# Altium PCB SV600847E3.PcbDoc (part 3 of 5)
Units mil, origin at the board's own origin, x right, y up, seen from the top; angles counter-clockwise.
Board outline 5404 x 2680 mil, 10 copper layers (Top Layer L1, Gnd-Plane - L2, Signals - L3, Gnd-Plane - L4, Pwr Plane - L5, Signals - L6, Gnd-Plane - L7, Signals - L8, Gnd-Plane - L9, Bottom Layer - L10), stack 57.8 mil thick; 517 components, 320 nets, 1784 pads, 1289 vias.
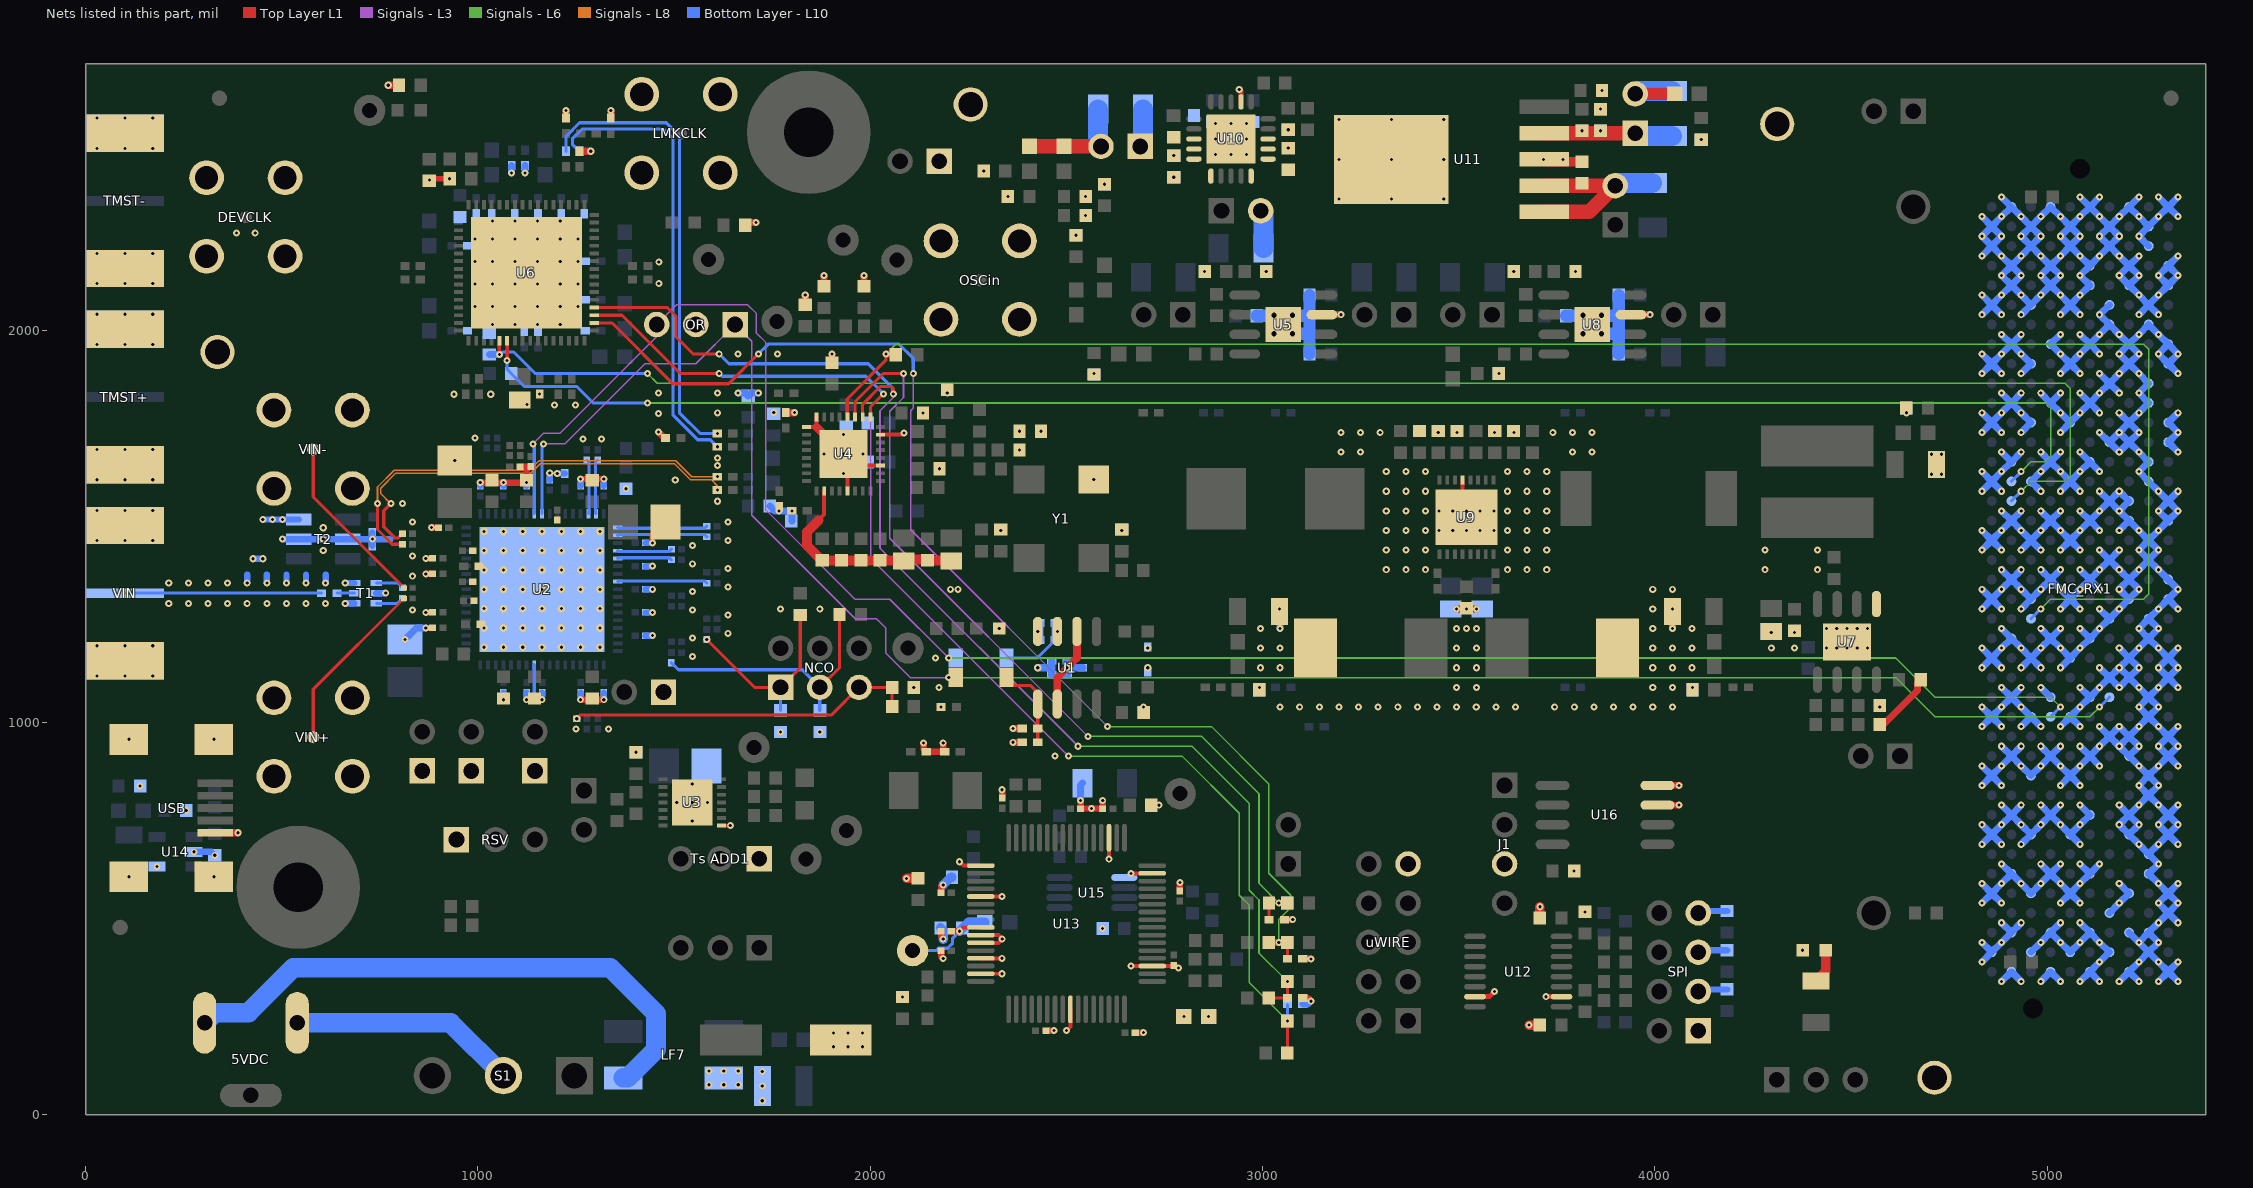
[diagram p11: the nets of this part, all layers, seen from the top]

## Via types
v1: diameter 18, hole 8, Top Layer L1 to Bottom Layer - L10, tented both sides, 1069 vias
v2: diameter 19.68, hole 7.87, Top Layer L1 to Bottom Layer - L10, 95 vias
v3: diameter 18, hole 8, Top Layer L1 to Bottom Layer - L10, tented bottom, 56 vias
v4: diameter 18, hole 8, Top Layer L1 to Bottom Layer - L10, tented top, 54 vias
v5: diameter 25.98, hole 12.99, Top Layer L1 to Bottom Layer - L10, tented top, 8 vias
v6: diameter 19.68, hole 7.87, Top Layer L1 to Bottom Layer - L10, tented top, 5 vias
v7: diameter 126, hole 106, Top Layer L1 to Bottom Layer - L10, tented top, 2 vias

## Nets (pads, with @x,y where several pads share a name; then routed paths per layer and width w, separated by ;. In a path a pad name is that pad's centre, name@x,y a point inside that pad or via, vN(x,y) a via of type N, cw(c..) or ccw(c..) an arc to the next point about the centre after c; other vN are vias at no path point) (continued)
GND: 12V.2 "Ts ADD1.1" C2.2 C8.2 C11.2 C16.1 C18.1 C19.1 C24.2 C25.2 C27.2 C39.2 C40.2 C41.1 C42.1 C43.1 C44.1 C45.1 C46.1 C47.1 C48.2 C49.2 C50.2 C51.1 C52.1 C53.1 C54.1 C55.1 C56.1 C57.1 C58.1 C59.2 C60.2 C61.2 C62.1 C63.1 C64.1 C65.1 C66.1 C67.1 C68.1 C69.1 C70.1 C71.1 C72.2 C75.1 C76.1 C77.1 C78.1 C80.1 C81.2 C82.1 C83.2 C84.1 C85.1 C86.2 C87.1 C88.2 C89.2 C91.2 C92.2 C93.2 C94.2 C95.1 C98.1 C99.1 C102.2 C103.2 C104.2 C105.2 C106.2 C107.2 C108.2 C109.2 C110.2 C111.2 C114.1 C115.2 C116.2 C120.2 C121.2 C122.2 C124.2 C125.2 C126.2 C127.2 C128.2 C129.2 C130.2 C143.2 C144.2 C145.2 C146.2 C147.2 C150.2 C151.2 C152.2 C153.2 C155.2 C156.1 C157.1 C158.2 C159.2 C160.2 C161.2 C162.2 C163.2 C164.2 C165.2 C166.2 C167.2 C168.2 C171.2 C172.2 C173.2 C176.2 C177.2 C178.2 C179.2 C180.2 C181.2 C182.2 C183.2 C184.2 C185.2 C186.2 C187.2 C188.2 C189.2 C190.2 C191.2 C193.2 C194.2 C195.2 C196.2 C197.2 C198.2 C199.2 C202.2 C203.2 C204.2 C206.2 C207.2 C208.2 C209.2 C213.1 C215.2 C218.2 C228.2 C229.2 D11.2 D12.2 DEVCLK.2 DEVCLK.3 DEVCLK.4 DEVCLK.5 FMC_RX1.A1 FMC_RX1.A4 FMC_RX1.A5 FMC_RX1.A8 FMC_RX1.A9 FMC_RX1.A12 FMC_RX1.A13 FMC_RX1.A16 FMC_RX1.A17 FMC_RX1.A20 FMC_RX1.A21 FMC_RX1.A24 FMC_RX1.A25 FMC_RX1.A28 FMC_RX1.A29 FMC_RX1.A32 FMC_RX1.A33 FMC_RX1.A36 FMC_RX1.A37 FMC_RX1.A40 FMC_RX1.B2 FMC_RX1.B3 FMC_RX1.B6 FMC_RX1.B7 FMC_RX1.B10 FMC_RX1.B11 FMC_RX1.B14 FMC_RX1.B15 FMC_RX1.B18 FMC_RX1.B19 FMC_RX1.B22 FMC_RX1.B23 FMC_RX1.B26 FMC_RX1.B27 FMC_RX1.B30 FMC_RX1.B31 FMC_RX1.B34 FMC_RX1.B35 FMC_RX1.B38 FMC_RX1.B39 FMC_RX1.C1 FMC_RX1.C4 FMC_RX1.C5 FMC_RX1.C8 FMC_RX1.C9 FMC_RX1.C12 FMC_RX1.C13 FMC_RX1.C16 FMC_RX1.C17 FMC_RX1.C20 FMC_RX1.C21 FMC_RX1.C24 FMC_RX1.C25 FMC_RX1.C28 FMC_RX1.C29 FMC_RX1.C32 FMC_RX1.C33 FMC_RX1.C36 FMC_RX1.C38 FMC_RX1.C40 FMC_RX1.D2 FMC_RX1.D3 FMC_RX1.D6 FMC_RX1.D7 FMC_RX1.D10 FMC_RX1.D13 FMC_RX1.D16 FMC_RX1.D19 FMC_RX1.D22 FMC_RX1.D25 FMC_RX1.D28 FMC_RX1.D37 FMC_RX1.D39 FMC_RX1.E1 FMC_RX1.E4 FMC_RX1.E5 FMC_RX1.E8 FMC_RX1.E11 FMC_RX1.E14 FMC_RX1.E17 FMC_RX1.E20 FMC_RX1.E23 FMC_RX1.E26 FMC_RX1.E29 FMC_RX1.E32 FMC_RX1.E35 FMC_RX1.E38 FMC_RX1.E40 FMC_RX1.F2 FMC_RX1.F3 FMC_RX1.F6 FMC_RX1.F9 FMC_RX1.F12 FMC_RX1.F15 FMC_RX1.F18 FMC_RX1.F21 FMC_RX1.F24 FMC_RX1.F27 FMC_RX1.F30 FMC_RX1.F33 FMC_RX1.F36 FMC_RX1.F39 FMC_RX1.G1 FMC_RX1.G4 FMC_RX1.G5 FMC_RX1.G8 FMC_RX1.G11 FMC_RX1.G14 FMC_RX1.G17 FMC_RX1.G20 FMC_RX1.G23 FMC_RX1.G26 FMC_RX1.G29 FMC_RX1.G32 FMC_RX1.G35 FMC_RX1.G38 FMC_RX1.G40 FMC_RX1.H2 FMC_RX1.H3 FMC_RX1.H6 FMC_RX1.H9 FMC_RX1.H12 FMC_RX1.H15 FMC_RX1.H18 FMC_RX1.H21 FMC_RX1.H24 FMC_RX1.H27 FMC_RX1.H30 FMC_RX1.H33 FMC_RX1.H36 FMC_RX1.H39 FMC_RX1.J1 FMC_RX1.J4 FMC_RX1.J5 FMC_RX1.J8 FMC_RX1.J11 FMC_RX1.J14 FMC_RX1.J17 FMC_RX1.J20 FMC_RX1.J23 FMC_RX1.J26 FMC_RX1.J29 FMC_RX1.J32 FMC_RX1.J35 FMC_RX1.J38 FMC_RX1.J40 FMC_RX1.K2 FMC_RX1.K3 FMC_RX1.K6 FMC_RX1.K9 FMC_RX1.K12 FMC_RX1.K15 FMC_RX1.K18 FMC_RX1.K21 FMC_RX1.K24 FMC_RX1.K27 FMC_RX1.K30 FMC_RX1.K33 FMC_RX1.K36 FMC_RX1.K39 GND1.1 GND2.1 GND3.1 GND.1 J1.3 L23.2 LD.2 LF2.2 LF3.1 LF7.4 LMKCLK.2 LMKCLK.3 LMKCLK.4 LMKCLK.5 MUXout.2 OR.2 R2.2 R3.1 R4.1 R5.1 R6.1 R10.2 R11.1 R12.1 R22.2 R23.2 R30.2 R33.2 R45.1 R49.1 R50.2 R51.1 R56.1 R65.1 R76.1 R77.1 R86.1 R87.1 R88.1 R89.1 R90.1 R96.1 R104.1 R116.1 R122.1 R128.1 R129.1 R135.1 R139.1 R140.1 R141.1 RSV.1 SPI.1 SPI.3 SPI.5 SPI.7 T1.1 T1.3 T1.5 T2.1 T2.2 T2.5 TMST+.2 TMST+.3 TMST+.4 TMST+.5 TMST-.2 TMST-.3 TMST-.4 TMST-.5 U1.4 U2.61 U2.69 U3.8 U3.15 U4.8 U4.9 U4.18 U4.21 U4.27 U4.31 U4.33 U5.3 U5.9 U6.65 U7.5 U7.9 U8.3 U8.9 U9.5 U9.17 U10.12 U10.21 U11.3 U11.6 U12.7 U12.10 U16.3 U16.4 uWIRE.9 VA12.1 VA19.1 Vbg.1 Vcmo.1 VD12.1 VIN+.2 VIN+.3 VIN+.4 VIN+.5 VIN-.2 VIN-.3 VIN-.4 VIN-.5 VIN.2 VIN.3 VIN.4 VIN.5 | length 24287.6
  Top Layer L1 w9: U3.8@1621.08,737.7 v1(1643.28,737.7)
  Top Layer L1 w10: U4.9@1837.39,1753.85 1862.98,1753.85 U4.8@1862.98,1779.45 ; 1867.87,1515.96 1882.66,1530.74 U4.18@1882.66,1590.47 ; U4.21@1941.72,1590.47 1941.72,1675.11 v2(1931.87,1684.96) 1961.4,1655.43 U4.27@2026.36,1655.43 ; U4.31@2026.36,1734.17 2082.5,1734.17 v1(2086.5,1738.17) ; U9.5@3510.16,1618.49 3510.16,1553.53 U9.17@3520,1543.68
  Top Layer L1 w13: U12.7@3541.76,301.55 3578.03,301.55 v1(3591.48,315) ; v1(3722.68,301.55) U12.10@3762.24,301.55
  Top Layer L1 w13.5: v1(2940.77,2614.17) 2945.27,2609.67 U10.12@2945.27,2582.49
  Top Layer L1 w15: v1(876.3,2383.18) 879.86,2386.74 v1(927.74,2386.74)
  Top Layer L1 w16: v1(867.03,1241.58) C51.1@884.65,1241.57 ; v1(867.03,1280.95) C41.1@884.65,1280.94 ; v1(867.03,1379.37) C42.1@884.65,1379.37 ; v1(867.03,1418.74) C54.1@884.65,1418.74 ; v1(882.03,1497.48) C44.1@899.65,1497.48 ; v1(1005.91,1612) v1(1124.02,1612) ; R22.2@1106.99,1653 R23.2@1135,1653.01 ; v1(1124.02,1058.65) v1(1163.39,1058.65) ; C50.2@1124.02,1618.3 1124.02,1653 ; v1(1261.81,1058.65) v1(1320.87,1058.65) ; v1(1261.81,1621.35) v1(1320.87,1621.35) ; v1(1444.74,1458.11) 1444.74,1477.62 C72.2@1478.52,1511.4
  Top Layer L1 w16.5: R116.1@3055.93,498 v1(3076.98,498) ; R128.1@3102.81,298 3115.87,298 v1(3123.87,290) ; R104.1@3102.81,398 v1(3123.87,398) ; U16.3@4006.86,790 v1(4062.16,790) ; U16.4@4006.86,840 v1(4062.16,840)
  Top Layer L1 w18: v1(771.3,2625) R45.1@798.94,2625 ; R50.2@1224.67,2541.37 v1(1224.67,2560.24) ; C114.1@1258.67,2456.68 v1(1287.54,2456.69) ; R51.1@1338.67,2541.37 v1(1338.67,2560.24) ; v1(1460.36,1741.48) 1475.84,1726 C215.2@1478.31,1726 ; R56.1@1681.06,2274.95 v1(1708.7,2274.95) ; C86.2@1834.31,2065.7 v1(1834.31,2090) ; C92.2@1882.39,2112.37 v1(1882.39,2140) ; C89.2@1902.35,1917.87 v1(1902.35,1940) ; R33.2@1984.18,2112.37 v1(1984.18,2140) ; v1(2363.82,950) R11.1@2387.63,950 ; v1(2363.82,985) C8.2@2387.63,985 ; U5.3@3151.43,2040 v1(3199.8,2040) ; v1(3494.47,1290) v1(3545.53,1290) ; U8.3@3939.43,2040 v1(3987.8,2040) ; R76.1@4573.56,995 4583,995 4670,1082 4670,1101.98 C162.2@4677.56,1109.54
  Top Layer L1 w19: C95.1@1784.89,1790.48 v1(1806.73,1790.48)
  Top Layer L1 w20: 1862.98,1753.85 v2(1931.87,1684.96)
  Top Layer L1 w24: v1(3679.37,229) R65.1@3707.12,229 ; C129.2@3707.12,502.06 v1(3707.12,530.79) ; U11.3@3718.22,2436 3724.13,2430.09 C196.2@3814,2430.09
  Top Layer L1 w25: 1867.87,1515.96 1838.54,1486.62 1838.54,1451.61 1876.42,1413.73 C82.1@2025.33,1413.73 C83.2@2083.62,1413.73 ; C83.2@2085.59,1411.76 C83.2@2083.62,1413.73 ; C80.1@2143.89,1415.7 2085.59,1415.7 C83.2@2083.62,1413.73 ; C80.1@2145.86,1413.73 2204.15,1413.73 C81.2@2206.12,1411.76
  Bottom Layer - L10 w9: 1143.7,1058.65 U2.61@1143.7,1147.09
  Bottom Layer - L10 w16: v1(411.81,1356.14) 411.81,1378 ; v1(426.57,1417.95) v1(451.57,1417.95) ; v1(451.58,1517.95) T2.1@543.06,1517.95 ; v1(461.81,1356.14) 461.81,1378 ; v1(501.58,1467.95) 777,1467.95 ; v1(511.81,1356.14) 511.81,1378 ; v1(561.81,1356.14) 561.81,1378 ; v1(611.81,1356.14) 611.81,1378 ; v1(661.81,1304.17) T1.1@685.57,1304.17 ; v1(661.81,1356.14) T1.3@685.57,1356.14 ; C229.2@730.85,1451.14 v1(730.85,1467.95) C228.2@730.85,1484.76 ; T1.5@741.09,1330.16 v1(764.85,1330.16) ; C45.1@1005.91,1603.73 v1(1005.91,1612) ; v1(1064.96,1058.65) C47.1@1064.96,1076.27 ; C46.1@1064.96,1603.73 v1(1064.96,1612) ; C58.1@1124.02,1076.27 v1(1124.02,1058.65) v1(1163.39,1058.65) C57.1@1163.39,1076.27 ; C55.1@1124.02,1603.73 v1(1124.02,1612) ; C56.1@1183.07,1618.73 v1(1183.07,1636.35) ; v1(1202.16,1635.31) C16.1@1221,1635.31 ; v1(1261.81,1058.65) C62.1@1261.81,1076.27 ; C70.1@1261.81,1603.73 v1(1261.81,1621.35) ; v1(1320.87,1058.65) C63.1@1320.87,1076.27 ; C69.1@1320.87,1603.73 v1(1320.87,1621.35) ; C64.1@1427.12,1221.89 v1(1444.74,1221.89) ; C65.1@1427.12,1280.95 v1(1444.74,1280.94) ; C66.1@1427.12,1340 v1(1444.74,1340) ; C67.1@1427.12,1399.05 v1(1444.74,1399.05) ; C68.1@1427.12,1458.11 v1(1444.74,1458.11) ; SPI.3@4111,315 4116.12,320.12 R139.1@4184.44,320.12 ; SPI.5@4111,415 4116.12,420.12 R140.1@4184.44,420.12 ; SPI.7@4111,515 4116.12,520.12 R141.1@4184.44,520.12
  Bottom Layer - L10 w16.5: R129.1@3102.81,282 3115.87,282 v1(3123.87,290)
  Bottom Layer - L10 w18: v1(814,1212.13) 843.44,1241.58 v1(867.03,1241.58) ; v1(1085.92,2401.26) C107.2@1085.92,2420.13 ; v1(1119.92,2401.26) C104.2@1119.92,2420.13 ; v1(1663.23,1840) 1681.52,1840 1688.96,1832.56 1696.4,1840 v1(1714.69,1840) ; C98.1@1744.08,1552.1 1756.18,1540 v1(1767.87,1540) v1(1800.25,1540) C94.2@1800.25,1514.27 ; v1(3045,1240) C183.2@3045,1290 ; 3119.93,2040 v1(3199.8,2040) ; 3907.93,2040 v1(3987.8,2040) ; v1(4044.85,1240) v1(4044.85,1290) ; v1(4834,390) FMC_RX1.K39@4859,415 ; v1(4834,440) FMC_RX1.K39@4859,415 ; v1(4834,540) FMC_RX1.K36@4859,565 ; v1(4834,590) FMC_RX1.K36@4859,565 ; v1(4834,690) FMC_RX1.K33@4859,715 ; v1(4834,740) FMC_RX1.K33@4859,715 ; v1(4834,840) FMC_RX1.K30@4859,865 ; v1(4834,890) FMC_RX1.K30@4859,865 ; v1(4834,990) FMC_RX1.K27@4859,1015 ; v1(4834,1040) FMC_RX1.K27@4859,1015 ; v1(4834,1140) FMC_RX1.K24@4859,1165 ; v1(4834,1190) FMC_RX1.K24@4859,1165 ; v1(4834,1290) FMC_RX1.K21@4859,1315 ; v1(4834,1340) FMC_RX1.K21@4859,1315 ; v1(4834,1440) FMC_RX1.K18@4859,1465 ; v1(4834,1490) FMC_RX1.K18@4859,1465 ; v1(4834,1590) FMC_RX1.K15@4859,1615 ; v1(4834,1640) FMC_RX1.K15@4859,1615 ; v1(4834,1740) FMC_RX1.K12@4859,1765 ; v1(4834,1790) FMC_RX1.K12@4859,1765 ; v1(4834,1890) FMC_RX1.K9@4859,1915 ; v1(4834,1940) FMC_RX1.K9@4859,1915 ; v1(4834,2040) FMC_RX1.K6@4859,2065 ; v1(4834,2090) FMC_RX1.K6@4859,2065 ; v1(4834,2190) FMC_RX1.K3@4859,2215 ; v1(4834,2290) FMC_RX1.K2@4859,2265 ; v1(4884,340) FMC_RX1.J40@4909,365 v1(4934,340) ; v1(4884,490) FMC_RX1.J38@4909,465 ; v1(4884,540) FMC_RX1.K36@4859,565 ; v1(4884,640) FMC_RX1.J35@4909,615 ; v1(4884,690) FMC_RX1.K33@4859,715 ; v1(4884,790) FMC_RX1.J32@4909,765 ; v1(4884,840) FMC_RX1.K30@4859,865 ; v1(4884,940) FMC_RX1.J29@4909,915 ; v1(4884,990) FMC_RX1.K27@4859,1015 ; v1(4884,1090) FMC_RX1.J26@4909,1065 ; v1(4884,1140) FMC_RX1.K24@4859,1165 ; v1(4884,1240) FMC_RX1.J23@4909,1215 ; v1(4884,1290) FMC_RX1.K21@4859,1315 ; v1(4884,1390) FMC_RX1.J20@4909,1365 ; v1(4884,1440) FMC_RX1.K18@4859,1465 ; v1(4884,1540) FMC_RX1.J17@4909,1515 ; v1(4884,1590) FMC_RX1.K15@4859,1615 ; v1(4884,1690) FMC_RX1.J14@4909,1665 ; v1(4884,1740) FMC_RX1.K12@4859,1765 ; v1(4884,1840) FMC_RX1.J11@4909,1815 ; v1(4884,1890) FMC_RX1.K9@4859,1915 ; v1(4884,1990) FMC_RX1.J8@4909,1965 ; v1(4884,2040) FMC_RX1.K6@4859,2065 ; v1(4884,2340) FMC_RX1.J1@4909,2315 ; v1(4934,490) FMC_RX1.J38@4909,465 ; v1(4934,690) FMC_RX1.H33@4959,715 ; v1(4934,790) FMC_RX1.J32@4909,765 ; v1(4934,940) FMC_RX1.J29@4909,915 ; v1(4934,990) FMC_RX1.H27@4959,1015 ; v1(4934,1090) FMC_RX1.J26@4909,1065 ; v1(4934,1140) FMC_RX1.H24@4959,1165 ; v1(4934,1290) FMC_RX1.H21@4959,1315 ; v1(4934,1390) FMC_RX1.J20@4909,1365 ; v1(4934,1440) FMC_RX1.H18@4959,1465 ; v1(4934,1540) FMC_RX1.J17@4909,1515 ; v1(4934,1690) FMC_RX1.J14@4909,1665 ; v1(4934,1740) FMC_RX1.H12@4959,1765 v1(4934,1790) FMC_RX1.J11@4909,1815 ; v1(4934,1840) FMC_RX1.J11@4909,1815 ; v1(4934,1890) FMC_RX1.H9@4959,1915 v1(4934,1940) FMC_RX1.J8@4909,1965 ; v1(4934,1990) FMC_RX1.J8@4909,1965 ; v1(4934,2040) FMC_RX1.H6@4959,2065 ; FMC_RX1.H39@4959,415 v1(4984,440) FMC_RX1.G38@5009,465 ; v1(4984,340) FMC_RX1.G40@5009,365 v1(5034,340) ; v1(4984,640) FMC_RX1.G35@5009,615 ; v1(4984,790) FMC_RX1.G32@5009,765 ; v1(4984,940) FMC_RX1.G29@5009,915 ; v1(4984,990) FMC_RX1.H27@4959,1015 ; v1(4984,1090) FMC_RX1.G26@5009,1065 ; v1(4984,1140) FMC_RX1.H24@4959,1165 ; v1(4984,1240) FMC_RX1.G23@5009,1215 ; v1(4984,1390) FMC_RX1.G20@5009,1365 ; v1(4984,1440) FMC_RX1.H18@4959,1465 ; v1(4984,1540) FMC_RX1.G17@5009,1515 ; v1(4984,1590) FMC_RX1.H15@4959,1615 v1(4984,1640) FMC_RX1.G14@5009,1665 ; v1(4984,1690) FMC_RX1.G14@5009,1665 ; v1(4984,1840) FMC_RX1.G11@5009,1815 ; v1(5034,490) FMC_RX1.G38@5009,465 ; v1(5034,540) FMC_RX1.F36@5059,565 ; v1(5034,640) FMC_RX1.G35@5009,615 ; v1(5034,790) FMC_RX1.G32@5009,765 ; v1(5034,840) FMC_RX1.F30@5059,865 ; v1(5034,940) FMC_RX1.G29@5009,915 ; v1(5034,990) FMC_RX1.F27@5059,1015 ; v1(5034,1140) FMC_RX1.F24@5059,1165 ; v1(5034,1240) FMC_RX1.G23@5009,1215 ; v1(5034,1290) FMC_RX1.F21@5059,1315 ; v1(5034,1390) FMC_RX1.G20@5009,1365 ; v1(5034,1440) FMC_RX1.F18@5059,1465 ; v1(5034,1540) FMC_RX1.G17@5009,1515 ; v1(5034,1590) FMC_RX1.F15@5059,1615 ; v1(5034,1690) FMC_RX1.G14@5009,1665 ; v1(5034,1740) FMC_RX1.F12@5059,1765 ; v1(5034,1840) FMC_RX1.G11@5009,1815 ; v1(5034,1890) FMC_RX1.F9@5059,1915 ; v1(5034,1990) FMC_RX1.G8@5009,1965 v1(5034,1940) FMC_RX1.F9@5059,1915 ; v1(5034,2040) FMC_RX1.F6@5059,2065 ; FMC_RX1.F9@5057,1913 v1@5082,1938 ; v1(5084,340) FMC_RX1.E40@5109,365 ; v1(5084,490) FMC_RX1.E38@5109,465 ; v1(5084,540) FMC_RX1.F36@5059,565 ; v1(5084,640) FMC_RX1.E35@5109,615 ; v1(5084,690) FMC_RX1.F33@5059,715 ; v1(5084,790) FMC_RX1.E32@5109,765 v1(5084,740) FMC_RX1.F33@5059,715 ; v1(5084,840) FMC_RX1.F30@5059,865 ; v1(5084,940) FMC_RX1.E29@5109,915 ; v1(5084,990) FMC_RX1.F27@5059,1015 ; v1(5084,1090) FMC_RX1.E26@5109,1065 ; v1(5084,1240) FMC_RX1.E23@5109,1215 ; v1(5084,1290) FMC_RX1.F21@5059,1315 ; v1(5084,1390) FMC_RX1.E20@5109,1365 ; v1(5084,1440) FMC_RX1.F18@5059,1465 ; v1(5084,1540) FMC_RX1.E17@5109,1515 ; v1(5084,1590) FMC_RX1.F15@5059,1615 ; v1(5084,1690) FMC_RX1.E14@5109,1665 ; v1(5084,1840) FMC_RX1.E11@5109,1815 ; v1(5084,1890) FMC_RX1.F9@5059,1915 ; v1(5084,1940) FMC_RX1.E8@5109,1965 ; v1(5084,1990) FMC_RX1.E8@5109,1965 ; v1(5084,2040) FMC_RX1.F6@5059,2065 ; v1(5084,2340) FMC_RX1.E1@5109,2315 ; v1(5134,340) FMC_RX1.E40@5109,365 ; v1(5134,640) FMC_RX1.E35@5109,615 ; v1(5134,890) FMC_RX1.E29@5109,915 ; v1(5134,990) FMC_RX1.D28@5159,965 ; v1(5134,1140) FMC_RX1.D25@5159,1115 ; v1(5134,1290) FMC_RX1.D22@5159,1265 ; v1(5134,1340) FMC_RX1.E20@5109,1365 ; v1(5134,1440) FMC_RX1.D19@5159,1415 ; v1(5134,1490) FMC_RX1.E17@5109,1515 ; v1(5134,1590) FMC_RX1.D16@5159,1565 ; v1(5134,1640) FMC_RX1.E14@5109,1665 ; v1(5134,1740) FMC_RX1.D13@5159,1715 ; v1(5134,1790) FMC_RX1.E11@5109,1815 ; v1(5134,1890) FMC_RX1.D10@5159,1865 ; v1(5134,1940) FMC_RX1.E8@5109,1965 ; v1(5134,2340) FMC_RX1.E1@5109,2315 ; FMC_RX1.D37@5159,515 v1(5184,540) FMC_RX1.C36@5209,565 v1(5184,590) ; FMC_RX1.D6@5159,2065 v1(5134,2040) FMC_RX1.D7@5159,2015 ; v1(5184,340) FMC_RX1.C40@5209,365 ; v1(5184,790) FMC_RX1.C32@5209,765 ; v1(5184,1140) FMC_RX1.D25@5159,1115 ; v1(5184,1190) FMC_RX1.C24@5209,1165 ; v1(5184,1440) FMC_RX1.D19@5159,1415 ; v1(5184,1490) FMC_RX1.C17@5209,1515 ; v1(5184,1790) FMC_RX1.C12@5209,1765 ; v1(5184,1840) FMC_RX1.D10@5159,1865 ; FMC_RX1.C38@5209,465 v1(5234,440) ; FMC_RX1.C25@5210,1115 5185,1140 FMC_RX1.C24@5210,1165 ; v1(5234,340) FMC_RX1.C40@5209,365 ; v1(5234,1440) FMC_RX1.B18@5259,1465 ; v1(5234,2040) FMC_RX1.B6@5259,2065 ; v1(5234,2190) FMC_RX1.C4@5209,2165 ; v1(5234,2340) FMC_RX1.C1@5209,2315 ; v1@5238,1436 FMC_RX1.B19@5263,1411 ; FMC_RX1.B3@5259,2215 v1(5234,2240) FMC_RX1.B2@5259,2265 ; v1(5284,340) FMC_RX1.A40@5309,365 ; v1(5284,2040) FMC_RX1.B6@5259,2065 ; v1(5284,2340) FMC_RX1.A1@5309,2315 ; v1(5334,340) FMC_RX1.A40@5309,365 ; v1(5334,390) FMC_RX1.A40@5309,365 ; v1(5334,490) FMC_RX1.A37@5309,515 ; v1(5334,590) FMC_RX1.A36@5309,565 ; v1(5334,690) FMC_RX1.A33@5309,715 ; v1(5334,790) FMC_RX1.A32@5309,765 ; v1(5334,890) FMC_RX1.A29@5309,915 ; v1(5334,990) FMC_RX1.A28@5309,965 ; v1(5334,1090) FMC_RX1.A25@5309,1115 ; v1(5334,1190) FMC_RX1.A24@5309,1165 ; v1(5334,1290) FMC_RX1.A21@5309,1315 ; v1(5334,1590) FMC_RX1.A16@5309,1565 ; v1(5334,1690) FMC_RX1.A13@5309,1715 v1(5334,1740) FMC_RX1.A12@5309,1765 v1(5334,1790) ; v1(5334,1890) FMC_RX1.A9@5309,1915 ; v1(5334,2190) FMC_RX1.A4@5309,2165 ; v1(5334,2290) FMC_RX1.A1@5309,2315 ; v1(5334,2340) FMC_RX1.A1@5309,2315 ; FMC_RX1.K39@4859,415 v1(4884,440) FMC_RX1.J38@4909,465 ; FMC_RX1.K36@4859,565 v1(4884,590) FMC_RX1.J35@4909,615 ; FMC_RX1.K33@4859,715 v1(4884,740) FMC_RX1.J32@4909,765 ; FMC_RX1.K30@4859,865 v1(4884,890) FMC_RX1.J29@4909,915 ; FMC_RX1.K27@4859,1015 v1(4884,1040) FMC_RX1.J26@4909,1065 ; FMC_RX1.K24@4859,1165 v1(4884,1190) FMC_RX1.J23@4909,1215 ; FMC_RX1.K21@4859,1315 v1(4884,1340) FMC_RX1.J20@4909,1365 ; FMC_RX1.K18@4859,1465 v1(4884,1490) FMC_RX1.J17@4909,1515 ; FMC_RX1.K15@4859,1615 v1(4884,1640) FMC_RX1.J14@4909,1665 ; FMC_RX1.K12@4859,1765 v1(4884,1790) FMC_RX1.J11@4909,1815 ; FMC_RX1.K9@4859,1915 v1(4884,1940) FMC_RX1.J8@4909,1965 ; FMC_RX1.K6@4859,2065 v1(4884,2090) FMC_RX1.J5@4909,2115 ; FMC_RX1.K3@4859,2215 v1(4884,2240) FMC_RX1.K2@4859,2265 ; FMC_RX1.K3@4859,2215 v1(4884,2190) FMC_RX1.J4@4909,2165 ; FMC_RX1.K3@4859,2215 v1(4834,2240) FMC_RX1.K2@4859,2265 ; FMC_RX1.K2@4859,2265 v1(4884,2290) FMC_RX1.J1@4909,2315 ; FMC_RX1.J35@4909,615 v1(4934,590) FMC_RX1.H36@4959,565 v1(4984,590) FMC_RX1.G35@5009,615 ; FMC_RX1.J32@4909,765 v1(4934,740) FMC_RX1.H33@4959,715 ; FMC_RX1.J29@4909,915 v1(4934,890) FMC_RX1.H30@4959,865 v1(4984,890) FMC_RX1.G29@5009,915 ; FMC_RX1.J26@4909,1065 v1(4934,1040) FMC_RX1.H27@4959,1015 ; FMC_RX1.J23@4909,1215 v1(4934,1190) FMC_RX1.H24@4959,1165 ; FMC_RX1.J20@4909,1365 v1(4934,1340) FMC_RX1.H21@4959,1315 ; FMC_RX1.J17@4909,1515 v1(4934,1490) FMC_RX1.H18@4959,1465 ; FMC_RX1.J5@4909,2115 v1(4934,2140) FMC_RX1.J4@4909,2165 ; FMC_RX1.J5@4909,2115 v1(4884,2140) FMC_RX1.J4@4909,2165 ; FMC_RX1.J5@4909,2115 v1(4934,2090) FMC_RX1.H6@4959,2065 ; FMC_RX1.J4@4909,2165 v1(4934,2190) FMC_RX1.H3@4959,2215 ; FMC_RX1.J1@4909,2315 v1(4934,2290) FMC_RX1.H2@4959,2265 ; FMC_RX1.H33@4959,715 v1(4984,740) FMC_RX1.G32@5009,765 ; FMC_RX1.H24@4959,1165 v1(4984,1190) FMC_RX1.G23@5009,1215 ; FMC_RX1.H21@4959,1315 v1(4984,1340) FMC_RX1.G20@5009,1365 ; FMC_RX1.H18@4959,1465 v1(4984,1490) FMC_RX1.G17@5009,1515 ; FMC_RX1.H6@4959,2065 v1(4984,2090) FMC_RX1.G5@5009,2115 ; FMC_RX1.H3@4959,2215 v1(4934,2240) FMC_RX1.H2@4959,2265 ; FMC_RX1.H3@4959,2215 v1(4984,2190) FMC_RX1.G4@5009,2165 ; FMC_RX1.H3@4959,2215 v1(4984,2240) FMC_RX1.H2@4959,2265 ; FMC_RX1.H2@4959,2265 v1(4984,2290) FMC_RX1.G1@5009,2315 v1(5034,2290) FMC_RX1.F2@5059,2265 ; FMC_RX1.G38@5009,465 v1(5034,440) FMC_RX1.F39@5059,415 v1(5084,440) FMC_RX1.E38@5109,465 ; FMC_RX1.G35@5009,615 v1(5034,590) FMC_RX1.F36@5059,565 ; FMC_RX1.G32@5009,765 v1(5034,740) FMC_RX1.F33@5059,715 ; FMC_RX1.G29@5009,915 v1(5034,890) FMC_RX1.F30@5059,865 ; FMC_RX1.G23@5009,1215 v1(5034,1190) FMC_RX1.F24@5059,1165 ; FMC_RX1.G20@5009,1365 v1(5034,1340) FMC_RX1.F21@5059,1315 ; FMC_RX1.G17@5009,1515 v1(5034,1490) FMC_RX1.F18@5059,1465 ; FMC_RX1.G14@5009,1665 v1(5034,1640) FMC_RX1.F15@5059,1615 ; FMC_RX1.G11@5009,1815 v1(5034,1790) FMC_RX1.F12@5059,1765 ; FMC_RX1.G5@5009,2115 v1(5034,2140) FMC_RX1.G4@5009,2165 ; FMC_RX1.G5@5009,2115 v1(4984,2140) FMC_RX1.G4@5009,2165 ; FMC_RX1.G5@5009,2115 v1(5034,2090) FMC_RX1.F6@5059,2065 ; FMC_RX1.G4@5009,2165 v1(5034,2190) FMC_RX1.F3@5059,2215 ; FMC_RX1.F36@5059,565 v1(5084,590) FMC_RX1.E35@5109,615 ; FMC_RX1.F30@5059,865 v1(5084,890) FMC_RX1.E29@5109,915 ; FMC_RX1.F27@5059,1015 v1(5084,1040) FMC_RX1.E26@5109,1065 ; FMC_RX1.F24@5059,1165 v1(5084,1190) FMC_RX1.E23@5109,1215 ; FMC_RX1.F21@5059,1315 v1(5084,1340) FMC_RX1.E20@5109,1365 ; FMC_RX1.F18@5059,1465 v1(5084,1490) FMC_RX1.E17@5109,1515 ; FMC_RX1.F15@5059,1615 v1(5084,1640) FMC_RX1.E14@5109,1665 ; FMC_RX1.F12@5059,1765 v1(5084,1790) FMC_RX1.E11@5109,1815 ; FMC_RX1.F6@5059,2065 v1(5084,2090) FMC_RX1.E5@5109,2115 v1(5084,2140) FMC_RX1.E4@5109,2165 ; FMC_RX1.F3@5059,2215 v1(5084,2240) FMC_RX1.F2@5059,2265 ; FMC_RX1.F3@5059,2215 v1(5034,2240) FMC_RX1.F2@5059,2265 ; FMC_RX1.F3@5059,2215 v1(5084,2190) FMC_RX1.E4@5109,2165 ; FMC_RX1.F2@5059,2265 v1(5084,2290) FMC_RX1.E1@5109,2315 ; FMC_RX1.E40@5109,365 v1(5134,390) FMC_RX1.D39@5159,415 v1(5134,440) FMC_RX1.E38@5109,465 ; FMC_RX1.E29@5109,915 v1(5134,940) FMC_RX1.D28@5159,965 ; FMC_RX1.E26@5109,1065 v1(5134,1090) FMC_RX1.D25@5159,1115 ; FMC_RX1.E23@5109,1215 v1(5134,1240) FMC_RX1.D22@5159,1265 ; FMC_RX1.E20@5109,1365 v1(5134,1390) FMC_RX1.D19@5159,1415 ; FMC_RX1.E17@5109,1515 v1(5134,1540) FMC_RX1.D16@5159,1565 ; FMC_RX1.E11@5109,1815 v1(5134,1840) FMC_RX1.D10@5159,1865 ; FMC_RX1.E8@5109,1965 v1(5134,1990) FMC_RX1.D7@5159,2015 ; FMC_RX1.E4@5109,2165 v1(5134,2190) FMC_RX1.D3@5159,2215 ; FMC_RX1.E1@5109,2315 v1(5134,2290) FMC_RX1.D2@5159,2265 ; FMC_RX1.D28@5159,965 v1(5184,990) FMC_RX1.C28@5209,965 ; FMC_RX1.D28@5159,965 v1(5184,940) ; FMC_RX1.D25@5159,1115 v1(5184,1090) FMC_RX1.C25@5209,1115 ; FMC_RX1.D22@5159,1265 v1(5184,1290) FMC_RX1.C21@5209,1315 ; FMC_RX1.D19@5159,1415 v1(5184,1390) FMC_RX1.C20@5209,1365 ; FMC_RX1.D16@5159,1565 v1(5184,1590) FMC_RX1.C16@5209,1565 v1(5184,1540) ; FMC_RX1.D16@5159,1565 v1(5184,1540) ; FMC_RX1.D13@5159,1715 v1(5184,1690) FMC_RX1.C13@5209,1715 ; FMC_RX1.D13@5159,1715 v1(5184,1740) ; FMC_RX1.D10@5159,1865 v1(5184,1890) FMC_RX1.C9@5209,1915 ; FMC_RX1.D7@5159,2015 v1(5184,1990) FMC_RX1.C8@5209,1965 ; FMC_RX1.D3@5159,2215 v1(5134,2240) FMC_RX1.D2@5159,2265 ; FMC_RX1.D3@5159,2215 v1(5184,2190) FMC_RX1.C4@5209,2165 ; FMC_RX1.D3@5159,2215 v1(5184,2240) FMC_RX1.D2@5159,2265 ; FMC_RX1.D2@5159,2265 v1(5184,2290) FMC_RX1.C1@5209,2315 ; v1(5184,940) FMC_RX1.C29@5209,915 ; v1(5184,940) FMC_RX1.C28@5209,965 ; v1(5184,1540) FMC_RX1.C17@5209,1515 ; v1(5184,1740) FMC_RX1.C12@5209,1765 ; v1(5184,1740) FMC_RX1.C13@5209,1715 ; FMC_RX1.C40@5209,365 v1(5234,390) FMC_RX1.B39@5259,415 ; FMC_RX1.C33@5209,715 v1(5184,740) FMC_RX1.C32@5209,765 ; FMC_RX1.C33@5209,715 v1(5234,740) FMC_RX1.C32@5209,765 ; FMC_RX1.C33@5209,715 v1(5234,690) FMC_RX1.B34@5259,665 ; FMC_RX1.C32@5209,765 v1(5234,790) FMC_RX1.B31@5259,815 ; FMC_RX1.C29@5209,915 v1(5234,940) FMC_RX1.C28@5209,965 ; FMC_RX1.C29@5209,915 v1(5234,890) FMC_RX1.B30@5259,865 ; FMC_RX1.C28@5209,965 v1(5234,990) FMC_RX1.B27@5259,1015 ; FMC_RX1.C25@5209,1115 v1(5234,1140) FMC_RX1.C24@5209,1165 ; FMC_RX1.C25@5209,1115 v1(5234,1090) FMC_RX1.B26@5259,1065 ; FMC_RX1.C24@5209,1165 v1(5234,1190) FMC_RX1.B23@5259,1215 ; FMC_RX1.C21@5209,1315 v1(5234,1340) FMC_RX1.C20@5209,1365 ; FMC_RX1.C21@5209,1315 v1(5184,1340) FMC_RX1.C20@5209,1365 ; FMC_RX1.C20@5209,1365 v1(5234,1390) FMC_RX1.B19@5259,1415 ; FMC_RX1.C17@5209,1515 v1(5234,1490) FMC_RX1.B18@5259,1465 ; FMC_RX1.C13@5209,1715 v1(5234,1690) FMC_RX1.B14@5259,1665 v1(5234,1640) FMC_RX1.B15@5259,1615 v1(5284,1590) FMC_RX1.A16@5309,1565 ; FMC_RX1.C13@5209,1715 v1(5234,1740) FMC_RX1.C12@5209,1765 ; FMC_RX1.C12@5209,1765 v1(5234,1790) FMC_RX1.B11@5259,1815 v1(5234,1840) FMC_RX1.B10@5259,1865 v1(5234,1890) FMC_RX1.C9@5209,1915 ; FMC_RX1.C9@5209,1915 v1(5184,1940) FMC_RX1.C8@5209,1965 ; FMC_RX1.C9@5209,1915 v1(5234,1940) FMC_RX1.C8@5209,1965 ; FMC_RX1.C8@5209,1965 v1(5234,1990) FMC_RX1.B7@5259,2015 v1(5284,1990) FMC_RX1.A8@5309,1965 ; FMC_RX1.C5@5209,2115 v1(5234,2090) FMC_RX1.B6@5259,2065 ; FMC_RX1.C5@5209,2115 v1(5184,2140) FMC_RX1.C4@5209,2165 ; FMC_RX1.C5@5209,2115 v1(5234,2140) FMC_RX1.C4@5209,2165 ; FMC_RX1.C1@5209,2315 v1(5234,2290) FMC_RX1.B2@5259,2265 ; v1(5234,440) FMC_RX1.B39@5259,415 ; v1(5234,440) FMC_RX1.B38@5259,465 ; FMC_RX1.B39@5259,415 v1(5284,390) FMC_RX1.A40@5309,365 ; FMC_RX1.B39@5259,415 v1(5284,440) FMC_RX1.B38@5259,465 ; FMC_RX1.B38@5259,465 v1(5284,490) FMC_RX1.A37@5309,515 ; FMC_RX1.B34@5259,665 v1(5284,640) FMC_RX1.B35@5259,615 v1(5284,590) FMC_RX1.A36@5309,565 ; FMC_RX1.B34@5259,665 v1(5284,690) FMC_RX1.A33@5309,715 ; FMC_RX1.B31@5259,815 v1(5284,790) FMC_RX1.A32@5309,765 ; FMC_RX1.B31@5259,815 v1(5284,840) FMC_RX1.B30@5259,865 ; FMC_RX1.B31@5259,815 v1(5234,840) FMC_RX1.B30@5259,865 ; FMC_RX1.B30@5259,865 v1(5284,890) FMC_RX1.A29@5309,915 ; FMC_RX1.B27@5259,1015 v1(5284,1040) FMC_RX1.B26@5259,1065 ; FMC_RX1.B27@5259,1015 v1(5284,990) FMC_RX1.A28@5309,965 ; FMC_RX1.B27@5259,1015 v1(5234,1040) FMC_RX1.B26@5259,1065 ; FMC_RX1.B26@5259,1065 v1(5284,1090) FMC_RX1.A25@5309,1115 ; FMC_RX1.B23@5259,1215 v1(5284,1190) FMC_RX1.A24@5309,1165 ; FMC_RX1.B23@5259,1215 v1(5284,1240) FMC_RX1.B22@5259,1265 ; FMC_RX1.B23@5259,1215 v1(5234,1240) FMC_RX1.B22@5259,1265 ; FMC_RX1.B22@5259,1265 v1(5284,1290) FMC_RX1.A21@5309,1315 ; FMC_RX1.B19@5259,1415 v1(5284,1390) FMC_RX1.A20@5309,1365 v1(5334,1340) FMC_RX1.A21@5309,1315 ; FMC_RX1.B19@5259,1415 v1(5284,1440) FMC_RX1.B18@5259,1465 ; FMC_RX1.B18@5259,1465 v1(5284,1490) FMC_RX1.A17@5309,1515 ; FMC_RX1.B6@5259,2065 v1(5284,2090) FMC_RX1.A5@5309,2115 ; FMC_RX1.B2@5259,2265 v1(5284,2290) FMC_RX1.A1@5309,2315 ; FMC_RX1.A37@5309,515 v1(5284,540) FMC_RX1.A36@5309,565 ; FMC_RX1.A37@5309,515 v1(5334,540) FMC_RX1.A36@5309,565 ; FMC_RX1.A33@5309,715 v1(5334,740) FMC_RX1.A32@5309,765 ; FMC_RX1.A33@5309,715 v1(5284,740) FMC_RX1.A32@5309,765 ; FMC_RX1.A29@5309,915 v1(5334,940) FMC_RX1.A28@5309,965 ; FMC_RX1.A29@5309,915 v1(5284,940) FMC_RX1.A28@5309,965 ; FMC_RX1.A25@5309,1115 v1(5334,1140) FMC_RX1.A24@5309,1165 ; FMC_RX1.A25@5309,1115 v1(5284,1140) FMC_RX1.A24@5309,1165 ; FMC_RX1.A17@5309,1515 v1(5334,1540) FMC_RX1.A16@5309,1565 ; FMC_RX1.A17@5309,1515 v1(5284,1540) FMC_RX1.A16@5309,1565 ; FMC_RX1.A9@5309,1915 v1(5334,1940) FMC_RX1.A8@5309,1965 ; FMC_RX1.A9@5309,1915 v1(5284,1940) FMC_RX1.A8@5309,1965 ; FMC_RX1.A5@5309,2115 v1(5284,2140) FMC_RX1.A4@5309,2165 ; FMC_RX1.A5@5309,2115 v1(5334,2140) FMC_RX1.A4@5309,2165
  Bottom Layer - L10 w19.5: v1(2427,1140) 2462.63,1140 ; C2.2@2432.31,1210.67 R3.1@2432.32,1254.36 ; R12.1@2462.63,1122 C11.2@2462.63,1158
  Bottom Layer - L10 w31.5: R49.1@2985.56,2037.44 3119.93,2037.44 ; v5(3029.38,2038.62) v5(3029.38,1991.38) 3119.93,1991.38 ; v5(3076.62,1991.38) v5(3076.62,2038.62) ; C128.2@3119.93,1940 C127.2@3119.93,2090 ; R77.1@3773.56,2037.44 3907.93,2037.44 ; v5(3817.38,2038.62) v5(3817.38,1991.38) 3907.93,1991.38 ; v5(3864.62,1991.38) v5(3864.62,2038.62) ; C161.2@3907.93,1940 C160.2@3907.93,2090
  other v1: 1724.85,36.28 1724.85,73.49 1589.24,76.96 1626.46,76.96 1663.67,76.96 1724.85,110.7 1589.24,112.01 1626.46,112.01 1663.67,112.01 1906.33,174.07 1943.54,174.07 1980.76,174.07 1906.33,209.12 1943.54,209.12 1980.76,209.12 2862.5,251 4376.94,420 3822,517.87 3794.26,622 2471,915 1403.28,924.59 1771.5,976.44 1871.5,976.44 1250.02,984.2 1332.65,984.2 2180.31,1040 2697.05,1040 3044.85,1040 3094.85,1040 3144.85,1040 3194.85,1040 3244.85,1040 3294.85,1040 3344.85,1040 3394.85,1040 3444.85,1040 3494.85,1040 3544.85,1040 3594.85,1040 3644.85,1040 3744.85,1040 3794.85,1040 3844.85,1040 3894.85,1040 3944.85,1040 3994.85,1040 4044.85,1040 4573.56,1040 2111.06,1090 2175,1090 2991.97,1090 3494.47,1090 3545.53,1090 3994.85,1090 4044.85,1090 4096.03,1090 2707.53,1140 2995,1140 3045,1140 3494.47,1140 3545.53,1140 3994.85,1140 4044.85,1140 4094.85,1140 2166,1165 1547,1168.84 2707.53,1190 2995,1190 3045,1190 3494.47,1190 3545.53,1190 3994.85,1190 4044.85,1190 4094.85,1190 4297,1190 4356,1190 1547,1215.89 1637,1227.89 4297,1229.62 4356,1229.62 2427,1232.52 2329.03,1240 2995,1240 3494.47,1240 3520,1240 3545.53,1240 3994.85,1240 4094.85,1240 1637,1274.95 833.57,1286.84 1547,1286.95 1771.5,1290 1871.5,1290 3043.15,1290 3520,1290 3994.85,1290 211.81,1304.17 261.81,1304.17 311.81,1304.17 361.81,1304.17 411.81,1304.17 461.81,1304.17 511.81,1304.17 561.81,1304.17 611.81,1304.17 1547,1334 2205,1340 2224.12,1340 3994.85,1340 4044.85,1340 1637,1346 211.81,1356.14 261.81,1356.14 311.81,1356.14 361.81,1356.14 833.57,1373.47 3315.39,1390 3365.39,1390 3415.39,1390 3624.61,1390 3674.61,1390 3724.61,1390 4281,1390 4415,1390 1637,1393.06 1547,1405.06 833.57,1424.64 605.65,1438.95 3315.39,1440 3365.39,1440 3415.39,1440 3624.61,1440 3674.61,1440 3724.61,1440 4281,1440 4415,1440 1547,1452.11 1637,1464.11 605.65,1467.95 3315.39,1490 3365.39,1490 3415.39,1490 3450.26,1490 3485.13,1490 3520,1490 3554.87,1490 3589.74,1490 3624.61,1490 3674.61,1490 3724.61,1490 605.65,1496.95 833.57,1511.27 1637,1511.17 476.58,1517.95 501.58,1517.95 3315.39,1540 3365.39,1540 3415.39,1540 3450.26,1540 3485.13,1540 3520,1540 3554.87,1540 3589.74,1540 3624.61,1540 3674.61,1540 3724.61,1540 807.81,1558.39 1610.22,1564.46 3315.39,1590 3365.39,1590 3415.39,1590 3624.61,1590 3674.61,1590 3724.61,1590 1377.24,1596.44 1503,1619 4705.5,1633.3 4730.8,1633.3 3315.39,1640 3365.39,1640 3415.39,1640 3624.61,1640 3674.61,1640 3724.61,1640 2176.7,1647.41 1610.22,1656.09 941,1668.13 1610.22,1674.46 4705.5,1684.2 4730.8,1684.2 3200,1690 3250,1690 3790,1690 3840,1690 1267.81,1723.61 1314.86,1723.61 992.12,1725.99 3200,1740 3250,1740 3300,1740 3448,1740 3496,1740 3591,1740 3641,1740 3740,1740 3790,1740 3840,1740 2435.5,1743 1460.36,1788.53 1610.22,1790 1754.18,1790.48 2134.7,1789.58 4641.38,1790 1194.96,1809.5 1249.01,1809.5 1124.92,1811 938.95,1837.32 1032.58,1837.31 1157.3,1838.05 1460.36,1840 1610.22,1840 2196.5,1840 2570,1890 3602.56,1890 1663.23,1940 1763.23,1940 1461.06,2119.97 2852.44,2150 3009.69,2150 3640.44,2150 3797.69,2150 1461.06,2174.02 2525,2242.56 384.47,2248.25 432.15,2248.25 2549.12,2292.5 3194.79,2334.81 3328.46,2334.81 3462.13,2334.81 2350.88,2341.5 2549.12,2341.5 2597,2372.62 2773.68,2390.44 2289.44,2406.01 3194.79,2436 3328.46,2436 3462.13,2436 3716,2436 3766,2436 3065.68,2464.56 4118.5,2486.37 3065.68,2511.44 3194.79,2537.19 3328.46,2537.19 3462.13,2537.19 3862,2563.95 3865.56,2612
  other v2: 1015.75,1192.36 1064.96,1192.36 1114.17,1192.36 1163.39,1192.36 1212.6,1192.36 1261.81,1192.36 1311.02,1192.36 1015.75,1241.57 1064.96,1241.57 1114.17,1241.57 1163.39,1241.57 1212.6,1241.57 1261.81,1241.57 1311.02,1241.57 1015.75,1290.79 1064.96,1290.79 1114.17,1290.79 1163.39,1290.79 1212.6,1290.79 1261.81,1290.79 1311.02,1290.79 1015.75,1340 1064.96,1340 1114.17,1340 1163.39,1340 1212.6,1340 1261.81,1340 1311.02,1340 1015.75,1389.21 1064.96,1389.21 1114.17,1389.21 1163.39,1389.21 1212.6,1389.21 1261.81,1389.21 1311.02,1389.21 1015.75,1438.43 1064.96,1438.43 1114.17,1438.43 1163.39,1438.43 1212.6,1438.43 1261.81,1438.43 1311.02,1438.43 1015.75,1487.64 1064.96,1487.64 1114.17,1487.64 1163.39,1487.64 1212.6,1487.64 1261.81,1487.64 1311.02,1487.64 1931.87,1634.96 1881.87,1684.96 1981.87,1684.96 1931.87,1734.96 1037.34,2015.5 1094.82,2015.5 1152.3,2015.5 1209.78,2015.5 992.06,2060.78 1037.34,2060.78 1094.82,2060.78 1152.3,2060.78 1209.78,2060.78 1255.06,2060.78 992.06,2118.26 1037.34,2118.26 1094.82,2118.26 1152.3,2118.26 1209.78,2118.26 1255.06,2118.26 992.06,2175.74 1037.34,2175.74 1094.82,2175.74 1152.3,2175.74 1209.78,2175.74 1255.06,2175.74 992.06,2233.22 1037.34,2233.22 1094.82,2233.22 1152.3,2233.22 1209.78,2233.22 1255.06,2233.22 1037.34,2278.5 1094.82,2278.5 1152.3,2278.5 1209.78,2278.5 2880.3,2448.63 2919.68,2448.63 2959.05,2448.63 2880.3,2488 2919.68,2488 2959.05,2488 2880.3,2527.37 2919.68,2527.37 2959.05,2527.37
  other v4: 29,1119.16 100,1119.16 171,1119.16 4437.98,1190 4463.99,1190 4490,1190 4516.01,1190 4542.02,1190 29,1196.16 100,1196.16 171,1196.16 4437.98,1240 4463.99,1240 4490,1240 4516.01,1240 4542.02,1240 29,1464.16 100,1464.16 171,1464.16 29,1541.16 100,1541.16 171,1541.16 29,1619.16 100,1619.16 171,1619.16 29,1696.16 100,1696.16 171,1696.16 29,1964.16 100,1964.16 171,1964.16 29,2041.16 100,2041.16 171,2041.16 29,2119.16 100,2119.16 171,2119.16 29,2196.16 100,2196.16 171,2196.16 29,2464.16 100,2464.16 171,2464.16 29,2541.16 100,2541.16 171,2541.16
  other v6: 1546.28,749.51 1506.91,796.76 1546.28,796.76 1585.65,796.76 1546.28,844
GND2: C118.2 C119.2 C131.2 C132.2 C133.2 C134.2 C135.2 C136.2 C137.2 C138.2 C139.2 C140.2 C141.2 C142.2 C200.2 C201.2 C205.2 C210.2 C211.2 C212.1 C214.2 L23.1 R67.1 R112.1 U13.1 U13.5 U13.10 U13.11 U13.13 U13.15 U13.25 U13.35 U13.47 U13.51 U14.2 U14.4 U15.5 USB.5 USB.6 USB.7 USB.8 USB.9 | length 1224.4
  Top Layer L1 w10: v1(2227.5,645.48) 2237.34,635.64 U13.1@2281.97,635.64 ; U13.15@2281.97,360.05 v1(2336,360.05) ; U13.13@2281.97,399.42 v1(2336,399.42) ; U13.11@2281.97,438.79 2326.59,438.79 v1(2336.44,448.63) 2326.59,458.47 U13.10@2281.97,458.47 ; U13.5@2281.97,556.9 v1(2336,556.9) ; v1(2500.47,215.03) 2510.31,224.87 U13.25@2510.31,269.5 ; v1(2608.74,652.04) U13.51@2608.74,706.5 ; v1(2664.51,379.73) U13.35@2718.98,379.73 C134.2@2773.44,379.73 ; v1(2664.51,615.95) U13.47@2718.98,615.95 ; C134.2@2773.45,381.5 2779.5,381.5 v1(2786,375)
  Top Layer L1 w16.5: v1(2136,947.84) 2136,932.66 C137.2@2142.66,926 C135.2@2190.28,926 2186,930.28 v1(2186,947.84) ; C133.2@2180.46,419.1 2180.46,404.7 v1(2186,399.16) ; C140.2@2180.46,468.32 2180.46,453.91 v1(2186,448.37) ; C142.2@2180.46,566.74 2180.46,581.14 v1(2186,586.68) ; C136.2@2336,808.01 v1(2336,829.07) ; C118.2@2447.72,215.03 v1(2468.77,215.03) ; v1(2536.3,801.51) C132.2@2536.3,781.24 C214.2@2592.6,781.24 v1(2592.6,801.51) ; C119.2@2675.46,210.03 v1(2696.52,210.03) ; C131.2@2789.45,571.41 v1(2789.45,592.47)
  Top Layer L1 w19.5: USB.5@330.71,719.44 v1(387.98,719.45)
  Top Layer L1 w24: v1(2092.74,603.08) R67.1@2121.47,603.08
  Bottom Layer - L10 w16.5: v1(275.94,670.86) 320.38,670.86 v1(329.24,662)
  Bottom Layer - L10 w18: v1(2536.3,801.51) 2536.3,841.38 C212.1@2540.91,846
  Bottom Layer - L10 w24: C139.2@2179.19,477.1 2186,470.29 v1(2186,448.37) ; v1(2186,586.68) 2205.32,606 C141.2@2208.44,606
  other v1: 2799.5,251 2081.91,300.8 2592.56,475 110.24,607.24 326.77,607.24 181.46,633.46 256.26,775.86 2564.45,781.24 2736,789.7 138.86,839 110.24,957.63 326.77,957.63
GND_OSC: C73.2 C74.1 OSCin.2 OSCin.3 OSCin.4 OSCin.5 R26.1 R28.1 R30.1 Y1.2
  other v1: 2332.8,1490 2641.2,1490 2569.68,1620 2380.38,1694.8 2380.38,1743
LM15851_OR_T0: D2.2 FMC_RX1.G27 OR.3 U2.25 | length 4977.3
  Signals - L3 w4: v1(1140.04,1710.8) 1167.24,1738 1209,1738 1455.5,1984.5 OR.3@1455.5,2015 1505.5,2065 1688,2065 1710,2043 1710,1993 1734,1969 1734,1542 1961,1315 2050,1315 v1(2200,1165)
  Signals - L6 w4: v1(2200,1165) 4614,1165 4714,1065 5009,1065 v3(5034,1040)
  Bottom Layer - L10 w8: v1(1140.04,1710.8) 1143.7,1707.14 U2.25@1143.7,1532.91 ; FMC_RX1.G27@5009,1015 v3(5034,1040)
LM15851_OR_T1: D4.2 FMC_RX1.D26 OR.1 U2.26 | length 5029.6
  Signals - L3 w4: v1(1167.05,1710.8) 1221.8,1710.8 1426,1915 1555.5,1915 OR.1@1655.5,2015 1698,1972.5 1698,1529 1962,1265 2016,1265 2040,1241 2040,1177 2102,1115 v1(2200,1115)
  Signals - L6 w4: v1(2200,1115) 4614,1115 4714,1015 5109,1015 v3(5134,1040)
  Bottom Layer - L10 w8: U2.26@1163.39,1532.91 1163.39,1707.14 v1(1167.05,1710.8) ; v3(5134,1040) FMC_RX1.D26@5159,1065
LMK04828_CSB: R68.1 R69.1 R98.1 R104.2 U6.18 | length 3106.1
  Top Layer L1 w8: U6.18@1296.79,2019.05 1341.95,2019.05 1497,1864 1639,1864 v1(1715,1940) ; R104.2@3063.44,398 R98.1@3063.44,440
  Top Layer L1 w18: R68.1@3016,440 R98.1@3063.44,440
  Signals - L3 w4: v1(2109.79,1890) 2109.79,1802.24 2103,1795.44 2103,1492 v1(2605,990)
  Signals - L6 w4: v1(2605,990) 2870,990 3016,844 3016,616 3072,560 3072,529 3041.56,498.56 v1(3041.56,440)
  Bottom Layer - L10 w8: v1(1715,1940) 1740,1965 2073.4,1965 2109.79,1928.61 v1(2109.79,1890) ; v1(3041.56,440) R69.1@3063.44,440
LMK04828_RESET: FMC_RX1.J16 R122.2 U6.5 | length 4506.4
  Top Layer L1 w9: v1(1054.66,1938.69) U6.5@1054.66,1973.77
  Signals - L6 w4: v1(1432,1890) 1457,1865 5046,1865 5059,1852 5059,1628 5046,1615 4959,1615 v3(4934,1590)
  Bottom Layer - L10 w8: v1(1054.66,1938.69) 1060.98,1945 1091,1945 1146,1890 v1(1432,1890) ; FMC_RX1.J16@4909,1565 v3(4934,1590)
  Bottom Layer - L10 w18: R122.2@1028.93,1938.69 v1(1054.66,1938.69)
LMK04828_SYNC: FMC_RX1.J15 R47.1 U6.6 | length 4298.5
  Top Layer L1 w9: v1(1074.35,1923.69) U6.6@1074.35,1973.77
  Signals - L6 w4: v1(1432.55,1815) 4996,1815 5009,1802 5009,1678 4996,1665 4959,1665 v3(4934,1640)
  Bottom Layer - L10 w8: v1(1074.35,1923.69) 1074.35,1901 R47.1@1085.35,1890 1118.35,1857 1252,1857 1294,1815 v1(1432.55,1815) ; FMC_RX1.J15@4909,1615 v3(4934,1640)
LMK_LMX_CLK: R102.1 R115.1 R121.1 R129.2 U4.1 U6.19 | length 3245.5
  Top Layer L1 w8: U6.19@1296.79,2038.73 1367.27,2038.73 1516,1890 v1(1615,1890) ; U4.1@2000.77,1779.45 2000.77,1805.21 v1(2033.79,1838.23) ; R102.1@3056.63,240 v1(3063.44,240) R115.1@3063.44,157.56
  Signals - L3 w4: v1(2033.79,1838.23) 2001,1805.44 2001,1419 v1(2505,915)
  Signals - L6 w4: v1(2505,915) 2795,915 2941,769 2941,560.44 2966,535.44 2966,337.44 v1(3063.44,240)
  Bottom Layer - L10 w8: v1(1615,1890) 1622,1883 1989.03,1883 v1(2033.79,1838.23) ; v1(3063.44,240) R129.2@3063.44,282
LMK_LMX_DATA: R101.1 R114.1 R120.1 R128.2 U4.2 U6.20 | length 3232.7
  Top Layer L1 w8: U6.20@1296.79,2058.42 1482.58,2058.42 1505,2036 1505,1984 1549,1940 v1(1615,1940) ; U4.2@1980.66,1784.34 1980.66,1811.97 2025.69,1857 2053,1857 2058.79,1851.21 v1(2058.79,1838.23) ; R114.1@3016,298 R128.2@3063.44,298 v1(3063.44,340)
  Signals - L3 w4: v1(2058.79,1838.23) 2058.79,1828.79 2025,1795 2025,1445 v1(2530,940)
  Signals - L6 w4: v1(2530,940) 2820,940 2966,794 2966,573 2991,548 2991,412.44 v1(3063.44,340)
  Bottom Layer - L10 w8: v1(1615,1940) 1640,1915 1995,1915 2058.79,1851.21 v1(2058.79,1838.23)
LMX2581_CE: FMC_RX1.H22 R117.1 U4.4 | length 4408.8
  Top Layer L1 w8: U4.4@1941.42,1782.45 1941.42,1825.05 2040,1923.63 v1(2040,1940) ; R117.1@2062.75,1940 R117.1@2064.75,1938
  Top Layer L1 w18: v1(2040,1940) R117.1@2062.75,1940
  Signals - L6 w4: v1(2040,1940) 2065,1965 5246,1965 5259,1952 5259,1328 5246,1315 5009,1315 v3(4984,1290)
  Bottom Layer - L10 w8: FMC_RX1.H22@4959,1265 v3(4984,1290)
LMX2581_LE: R97.1 R113.1 R116.2 R119.1 U4.3 | length 2244.9
  Top Layer L1 w8: U4.3@1961.05,1782.36 1961.05,1817.81 2033.24,1890 v1(2084.79,1890) ; R116.2@3016.56,498 R113.1@3016.56,540 R97.1@3063.44,540
  Signals - L3 w4: v1(2084.79,1890) 2084.79,1828.79 2050,1794 2050,1470 v1(2555,965)
  Signals - L6 w4: v1(2555,965) 2845,965 2991,819 2991,590.56 v1(3041.56,540)
  Bottom Layer - L10 w8: v1(3041.56,540) R119.1@3063.44,540
LMX_OUTA_N: C101.1 C112.2 | length 1179.6
  Bottom Layer - L10 w8: C112.2@1224.67,2456.69 1224.67,2495.17 1258.88,2529.38 1480.13,2529.38 1513.5,2496 1513.5,1790.5 1566.73,1737.27 v4(1610.22,1737.27)
LMX_OUTA_P: C96.2 C113.2 | length 1168
  Bottom Layer - L10 w8: C113.2@1258.67,2456.69 1240.67,2474.68 1240.67,2488.54 1265.51,2513.38 1473.5,2513.38 1497.5,2489.38 1497.5,1783.87 1560.1,1721.27 1592.22,1721.27 v4(1610.22,1703.27)
LMX_OUTB_N: C33.2 C100.1 | length 1098.5
  Top Layer L1 w8: v1(778,1558.39) 760,1540.39 760,1499.04 788.04,1471 797.14,1471 C33.2@807.59,1481.45
  Signals - L8 w4: v1(778,1558.39) 752,1584.39 752,1597.6 790.04,1635.65 1134.58,1635.65 1158.94,1660 1500.96,1660 1541.69,1619.27 1595.23,1619.27 1610.22,1604.28 v1(1610.22,1593.27)
LMX_OUTB_P: C32.2 C97.2 | length 1098.7
  Top Layer L1 w8: v1(744,1558.39) 744,1492.41 781.41,1455 807.04,1455 C32.2@807.59,1454.45
  Signals - L8 w4: v1(744,1558.39) 744,1600.92 786.73,1643.65 1131.27,1643.65 1155.62,1668 1504.28,1668 1545,1627.27 v1(1610.22,1627.27)
NCO_0: NCO.1 R6.2 R7.1 R136.1 | length 502.4
  Top Layer L1 w8: v1(1583.2,1211.93) 1705.13,1090 NCO.1@1771.5,1090 1821.5,1140 R136.1@1821.5,1274.44
  Bottom Layer - L10 w8: R6.2@1771.5,1031.56 NCO.1@1771.5,1090
NCO_1: NCO.3 R5.2 R8.1 R137.1 | length 669.5
  Top Layer L1 w8: NCO.3@1871.5,1090 1921.5,1140 R137.1@1921.5,1276
  Bottom Layer - L10 w8: R8.1@1493.2,1152.88 1511.27,1134.81 1826.69,1134.81 NCO.3@1871.5,1090 R5.2@1871.5,1031.56
NCO_2: NCO.5 R4.2 R9.1 R138.1 | length 886.1
  Top Layer L1 w8: v1(1251.86,1010.18) 1261.67,1020 1901.5,1020 NCO.5@1971.5,1090 R4.2@2055.94,1090 R138.1@2055.94,1041
Net1V2ADC_INT_2: 1V2ADC_INT.2 C172.1 R83.2 U10.5 U10.6 U10.7 U10.8 | length 97.4
  Bottom Layer - L10 w51: 1V2ADC_INT.2@2995.26,2305 3002.35,2297.91 R83.2@3002.35,2210.56
Net1V2ADC_LDO_1: 1V2ADC_LDO.1 C185.1 C195.1 R84.1 R85.2 U10.1 U10.18 U10.19 U10.20 | length 97.4
  Bottom Layer - L10 w51: 1V2ADC_LDO.1@2688.27,2469 2695.35,2476.09 R84.1@2695.35,2563.44
  other v1: 2773.68,2445.56
Net1V2ADC_LDO_2: 1V2ADC_LDO.2 L15.1 L16.1 R84.2 | length 279.6
  Top Layer L1 w37: L15.1@2406,2469 L16.1@2494,2469 1V2ADC_LDO.2@2588.27,2469
  Bottom Layer - L10 w51: R84.2@2581.18,2563.44 2581.18,2476.09 1V2ADC_LDO.2@2588.27,2469
Net1V9ADC_1: 1V9ADC.1 C192.1 C198.1 C204.1 R92.1 R93.2 U11.4 | length 377.2
  Top Layer L1 w37: U11.4@3718.22,2502.93 1V9ADC.1@3950,2502.93
  Bottom Layer - L10 w24: v1(3814,2508.83) v1(3862,2508.83)
  Bottom Layer - L10 w51: 1V9ADC.1@3950,2502.93 3957.09,2495.84 R92.1@4044.44,2495.84
Net1V9ADC_2: 1V9ADC.2 L18.1 R92.2 | length 197.9
  Top Layer L1 w31.5: 1V9ADC.2@3950,2602.93 L18.1@4050.5,2602.93
  Bottom Layer - L10 w51: 1V9ADC.2@3950,2602.93 3957.09,2610.02 R92.2@4044.44,2610.02
Net1V9INT_2: 1V9INT.2 C196.1 R95.2 U11.1 U11.2 | length 487
  Top Layer L1 w37: U11.1@3718.22,2302.14 3833.07,2302.14 1V9INT.2@3899,2369.07 U11.2@3718.22,2369.07
  Bottom Layer - L10 w51: 1V9INT.2@3899,2369.07 3906.09,2376.16 R95.2@3993.44,2376.16
Net3P3USB_1: 3P3USB.1 C139.1 C140.1 L24.2 U13.9 | length 301.4
  Top Layer L1 w10: v1(2227.5,468.31) 2237.34,478.16 U13.9@2281.97,478.16
  Top Layer L1 w16.5: C140.1@2206.44,468.32 v1(2227.5,468.31)
  Bottom Layer - L10 w8: 3P3USB.1@2108,419 2168,419 2174,425 2197,425 2210,438 2210,450.81 v1(2227.5,468.31)
  Bottom Layer - L10 w24: v1(2227.5,468.31) 2250.18,491 L24.2@2292.5,491
Net5VDC_1: 5VDC.1 S1.2 | length 581.5
  Bottom Layer - L10 w50: 5VDC.1@539.37,235 930.2,235 S1.2@1065,100.2
Net5VDC_2: 5VDC.2 LF7.1 | length 1462.5
  Bottom Layer - L10 w50: 5VDC.2@303.15,235 329.15,261 415,261 529.51,375.51 1336.79,375.51 1454,258.31 1454,166.89 1381.6,94.49 LF7.1@1370.55,94.49
Net12V_1: 12V.1 R94.1 | length 88.2
  Top Layer L1 w25: R94.1@4411,342.15 4436,367.15 12V.1@4436,420
NetC1_2: C1.2 VIN+.1 | length 449.2
  Top Layer L1 w8: VIN+.1@580,963.32 580,1085.13 C1.2@811.52,1316.66
NetC2_1: C2.1 D2.1 R3.2 U1.3 | length 187.3
  Bottom Layer - L10 w8: D2.1@2346.95,1165 2426.02,1165 C2.1@2471.68,1210.67
  Bottom Layer - L10 w19.5: C2.1@2471.68,1210.67 R3.2@2471.69,1254.36
  other v1: 2477,1232.52
NetC3_2: C3.2 T1.6 | length 71.7
  Bottom Layer - L10 w8: T1.6@741.09,1304.17 795.1,1304.17 C3.2@807.59,1316.66
NetC4_1: C4.1 T1.2 | length 44.9
  Bottom Layer - L10 w8: C4.1@640.68,1330.16 T1.2@685.57,1330.16
NetC4_2: C4.2 VIN.1 | length 501.3
  Bottom Layer - L10 w8: VIN.1@100,1330.16 C4.2@601.31,1330.16
NetC5_2: C5.2 T1.4 | length 71.7
  Bottom Layer - L10 w8: T1.4@741.09,1356.14 795.1,1356.14 C5.2@807.59,1343.66
NetC6_1: C6.1 VIN-.1 | length 449.2
  Top Layer L1 w8: VIN-.1@580,1697 580,1575.18 C6.1@811.52,1343.66
NetC7_2: C7.2 U2.33 | length 139.9
  Bottom Layer - L10 w8: U2.33@1301.18,1532.91 1299.34,1534.76 1299.34,1664.32 C7.2@1304.84,1669.81
NetC8_1: C8.1 D4.1 R11.2 U1.5 | length 222.2
  Top Layer L1 w8: D4.1@2346.95,1115 2366.95,1095 2408,1095 2427,1076 U1.5@2427,1047.48 C8.1@2427,985 R11.2@2427,950
NetC9_2: C9.2 U2.32 | length 139.9
  Bottom Layer - L10 w8: C9.2@1277.84,1669.81 1283.34,1664.31 1283.34,1534.76 U2.32@1281.5,1532.91
NetC10_2: C10.2 U2.36 | length 229.9
  Bottom Layer - L10 w8: U2.36@1356.3,1477.8 1358.14,1479.64 1577.7,1479.64 C10.2@1583.2,1474.14
NetC11_1: C11.1 R1.1 R12.2 U1.2 U1.6 | length 281.1
  Top Layer L1 w19.5: U1.6@2477,1047.48 2477,1115 v1(2502,1140) 2527,1165 U1.2@2527,1232.52
  Bottom Layer - L10 w19.5: R12.2@2502,1122 C11.1@2502,1158 ; v1(2502,1140) R1.1@2541.32,1140
NetC12_2: C12.2 U2.35 | length 229.9
  Bottom Layer - L10 w8: U2.35@1356.3,1497.48 1358.14,1495.64 1577.7,1495.64 C12.2@1583.2,1501.14
NetC13_2: C13.2 U2.39 | length 139.9
  Bottom Layer - L10 w8: U2.39@1356.3,1418.74 1358.14,1420.58 1487.7,1420.58 C13.2@1493.2,1415.08
NetC14_2: C14.2 U2.38 | length 139.9
  Bottom Layer - L10 w8: U2.38@1356.3,1438.43 1358.14,1436.58 1487.7,1436.58 C14.2@1493.2,1442.08
NetC15_2: C15.2 U2.42 | length 229.9
  Bottom Layer - L10 w8: U2.42@1356.3,1359.68 1358.14,1361.53 1577.7,1361.53 C15.2@1583.2,1356.03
